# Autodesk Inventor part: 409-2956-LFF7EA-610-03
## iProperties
Created: 2011-01
Part Number: 409-2956-LFF7EA-610-03
Cost Center: 0 lbmass
Material: A36 STEEL PLATE
Document SubType Name: Sheet Metal
Designer: S. Boerckel
Authority: 0 in^3
Mass: 3944.57 g
Surface Area: 925.805 cm^2
Volume: 501.854 cm^3
Density: 7.86 g/cm^3
Flat Pattern Width: 8.89 cm
Flat Pattern Length: 44.45 cm
Flat Pattern Area: 395.161 cm^2
Sheet Metal Rule: 1/2"Thk
Description: BASE PLATE
SaveDate: 2008-01-15
SaveTime: 10:24
FileName: Sheet Metal
Wide: =<Flat Pattern Width>cm
Length: =<Flat Pattern Length>cm
Thickness: 0.5000 in
SMR: =<Sheet Metal Rule> - <Material>
Author: S. Boerckel
Revision Number: 0
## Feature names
1. Plate1
